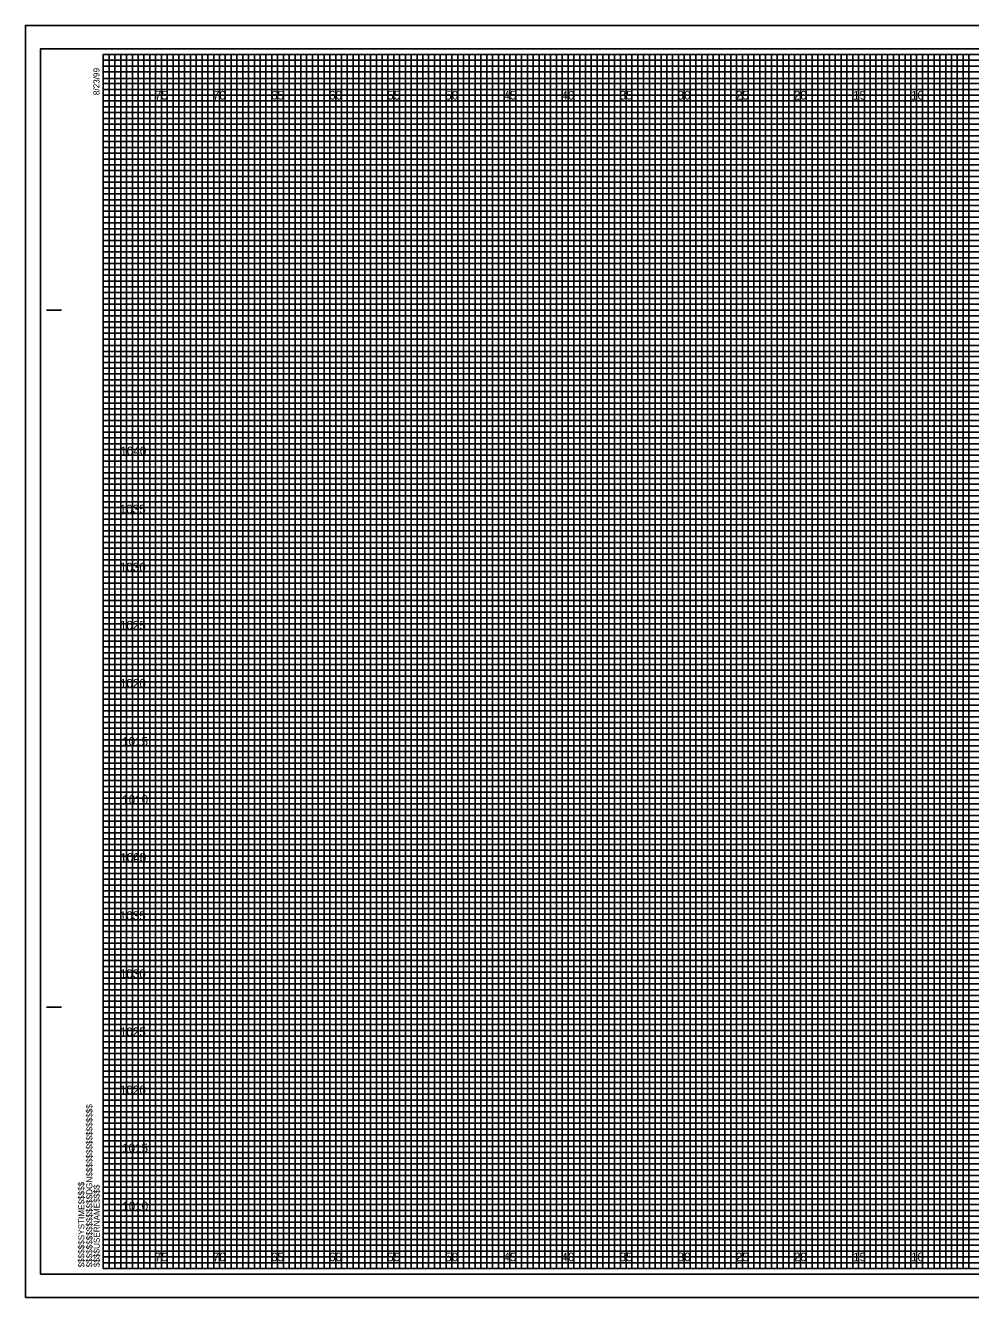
# Model space of a CAD drawing. Extents: x -7 to 162, y -2 to 987.
# Drawn here: x -6.7 to 74.6, y 217.5 to 327 of the extents above; entities that cross this region are included whole.
import ezdxf

# ---------------------------------------------------------------- set-up
doc = ezdxf.new("R2010")
doc.units = 0
for name, color, linetype in [('Exist Cross Section Cell', 7, 'Continuous'), ('Exist XS Center Line Elevation Label', 7, 'Continuous'), ('Exist XS Ground Line', 7, 'Continuous'), ('Prop CMT Concrete Structures', 7, 'Continuous'), ('Prop CMT Guardrail Widen Shoulder', 7, 'Continuous'), ('Prop CMT Pvmt Course 1', 7, 'Continuous'), ('Prop CMT Pvmt Surface', 7, 'Continuous'), ('Prop CMT Shld Paved Course 1', 7, 'Continuous'), ('Prop CMT Slope Grass', 7, 'Continuous'), ('Prop CMT Subgrade Earthwork', 7, 'Continuous'), ('Typical Text Label CELL', 7, 'Continuous')]:
    doc.layers.add(name, color=color, linetype=linetype)

msp = doc.modelspace()

# ---------------------------------------------------------------- linework, layer by layer
at = {"layer": 'Exist XS Center Line Elevation Label'}
for points in [[(0, 324.5), (2.5, 324.5), (2.5, 220), (7.5, 220), (7.5, 324.5), (12.5, 324.5), (12.5, 220), (17.5, 220), (17.5, 324.5), (22.5, 324.5), (22.5, 220), (27.5, 220), (27.5, 324.5), (32.5, 324.5), (32.5, 220), (37.5, 220), (37.5, 324.5), (42.5, 324.5), (42.5, 220), (47.5, 220), (47.5, 324.5), (52.5, 324.5), (52.5, 220), (57.5, 220), (57.5, 324.5), (62.5, 324.5), (62.5, 220), (67.5, 220), (67.5, 324.5), (72.5, 324.5), (72.5, 220), (77.5, 220)], [(0, 322), (137.5, 322)], [(0, 312.5), (160, 312.5), (160, 317.5), (0, 317.5)], [(0, 302.5), (160, 302.5), (160, 307.5), (0, 307.5)], [(0, 292.5), (160, 292.5), (160, 297.5), (0, 297.5)], [(0, 282.5), (160, 282.5), (160, 287.5), (0, 287.5)], [(0, 272.5), (160, 272.5), (160, 277.5), (0, 277.5)], [(0, 262.5), (160, 262.5), (160, 267.5), (0, 267.5)], [(0, 252.5), (160, 252.5), (160, 257.5), (0, 257.5)], [(0, 242.5), (160, 242.5), (160, 247.5), (0, 247.5)], [(0, 232.5), (160, 232.5), (160, 237.5), (0, 237.5)], [(0, 222.5), (160, 222.5), (160, 227.5), (0, 227.5)]]:
    msp.add_lwpolyline(points, dxfattribs=at)
at = {"layer": 'Exist XS Ground Line'}
for p, q in [((5, 324.5), (0, 324.5)), ((5, 220), (5, 324.5)), ((15, 324.5), (10, 324.5)), ((10, 324.5), (10, 220)), ((15, 220), (15, 324.5)), ((25, 324.5), (20, 324.5)), ((20, 324.5), (20, 220)), ((25, 220), (25, 324.5)), ((35, 324.5), (30, 324.5)), ((30, 324.5), (30, 220)), ((35, 220), (35, 324.5)), ((45, 324.5), (40, 324.5)), ((40, 324.5), (40, 220)), ((45, 220), (45, 324.5)), ((55, 324.5), (50, 324.5)), ((50, 324.5), (50, 220)), ((55, 220), (55, 324.5)), ((65, 324.5), (60, 324.5)), ((60, 324.5), (60, 220)), ((65, 220), (65, 324.5)), ((75, 324.5), (70, 324.5)), ((70, 324.5), (70, 220)), ((10, 220), (5, 220)), ((20, 220), (15, 220)), ((30, 220), (25, 220)), ((40, 220), (35, 220)), ((50, 220), (45, 220)), ((60, 220), (55, 220)), ((70, 220), (65, 220))]:
    msp.add_line(p, q, dxfattribs=at)
for points in [[(0, 320), (160, 320), (160, 315), (0, 315)], [(0, 310), (160, 310), (160, 305), (0, 305)], [(0, 300), (160, 300), (160, 295), (0, 295)], [(0, 290), (160, 290), (160, 285), (0, 285)], [(0, 280), (160, 280), (160, 275), (0, 275)], [(0, 270), (160, 270), (160, 265), (0, 265)], [(0, 260), (160, 260), (160, 255), (0, 255)], [(0, 250), (160, 250), (160, 245), (0, 245)], [(0, 240), (160, 240), (160, 235), (0, 235)], [(0, 230), (160, 230), (160, 225), (0, 225)]]:
    msp.add_lwpolyline(points, dxfattribs=at)
at = {"layer": 'Prop CMT Concrete Structures'}
for p, q in [((5, 220), (5, 324.5)), ((10, 220), (10, 324.5)), ((15, 220), (15, 324.5)), ((20, 220), (20, 324.5)), ((25, 220), (25, 324.5)), ((30, 220), (30, 324.5)), ((35, 220), (35, 324.5)), ((40, 220), (40, 324.5)), ((45, 220), (45, 324.5)), ((50, 220), (50, 324.5)), ((55, 220), (55, 324.5)), ((60, 220), (60, 324.5)), ((65, 220), (65, 324.5)), ((70, 220), (70, 324.5)), ((0, 320), (160, 320)), ((0, 315), (160, 315)), ((0, 310), (160, 310)), ((0, 305), (160, 305)), ((0, 300), (160, 300)), ((0, 295), (160, 295)), ((0, 290), (160, 290)), ((0, 285), (160, 285)), ((0, 280), (160, 280)), ((0, 275), (160, 275)), ((0, 270), (160, 270)), ((0, 265), (160, 265)), ((0, 260), (160, 260)), ((0, 255), (160, 255)), ((0, 250), (160, 250)), ((0, 245), (160, 245)), ((0, 240), (160, 240)), ((0, 235), (160, 235)), ((0, 230), (160, 230)), ((0, 225), (160, 225))]:
    msp.add_line(p, q, dxfattribs=at)
at = {"layer": 'Prop CMT Guardrail Widen Shoulder'}
for p, q in [((161.65, 327), (-6.7, 327)), ((-6.7, 327), (-6.7, 217.5)), ((-6.7, 217.5), (161.65, 217.5))]:
    msp.add_line(p, q, dxfattribs=at)
at = {"layer": 'Prop CMT Pvmt Course 1'}
msp.add_lwpolyline([(-6.7, 217.5), (161.65, 217.5), (161.65, 327), (-6.7, 327)], close=True, dxfattribs=at)
at = {"layer": 'Prop CMT Pvmt Surface'}
for points in [[(0, 220), (0.5, 220), (0.5, 324.5), (1, 324.5), (1, 220)], [(1, 220), (1.5, 220), (1.5, 324.5), (2, 324.5), (2, 220)], [(2.5, 220), (3, 220), (3, 324.5), (3.5, 324.5), (3.5, 220)], [(3.5, 220), (4, 220), (4, 324.5), (4.5, 324.5), (4.5, 220)], [(5, 220), (5.5, 220), (5.5, 324.5), (6, 324.5), (6, 220)], [(6, 220), (6.5, 220), (6.5, 324.5), (7, 324.5), (7, 220)], [(7.5, 220), (8, 220), (8, 324.5), (8.5, 324.5), (8.5, 220)], [(8.5, 220), (9, 220), (9, 324.5), (9.5, 324.5), (9.5, 220)], [(10, 220), (10.5, 220), (10.5, 324.5), (11, 324.5), (11, 220)], [(11, 220), (11.5, 220), (11.5, 324.5), (12, 324.5), (12, 220)], [(12.5, 220), (13, 220), (13, 324.5), (13.5, 324.5), (13.5, 220)], [(13.5, 220), (14, 220), (14, 324.5), (14.5, 324.5), (14.5, 220)], [(15, 220), (15.5, 220), (15.5, 324.5), (16, 324.5), (16, 220)], [(16, 220), (16.5, 220), (16.5, 324.5), (17, 324.5), (17, 220)], [(17.5, 220), (18, 220), (18, 324.5), (18.5, 324.5), (18.5, 220)], [(18.5, 220), (19, 220), (19, 324.5), (19.5, 324.5), (19.5, 220)], [(20, 220), (20.5, 220), (20.5, 324.5), (21, 324.5), (21, 220)], [(21, 220), (21.5, 220), (21.5, 324.5), (22, 324.5), (22, 220)], [(22.5, 220), (23, 220), (23, 324.5), (23.5, 324.5), (23.5, 220)], [(23.5, 220), (24, 220), (24, 324.5), (24.5, 324.5), (24.5, 220)], [(25, 220), (25.5, 220), (25.5, 324.5), (26, 324.5), (26, 220)], [(26, 220), (26.5, 220), (26.5, 324.5), (27, 324.5), (27, 220)], [(27.5, 220), (28, 220), (28, 324.5), (28.5, 324.5), (28.5, 220)], [(28.5, 220), (29, 220), (29, 324.5), (29.5, 324.5), (29.5, 220)], [(30, 220), (30.5, 220), (30.5, 324.5), (31, 324.5), (31, 220)], [(31, 220), (31.5, 220), (31.5, 324.5), (32, 324.5), (32, 220)], [(32.5, 220), (33, 220), (33, 324.5), (33.5, 324.5), (33.5, 220)], [(33.5, 220), (34, 220), (34, 324.5), (34.5, 324.5), (34.5, 220)], [(35, 220), (35.5, 220), (35.5, 324.5), (36, 324.5), (36, 220)], [(36, 220), (36.5, 220), (36.5, 324.5), (37, 324.5), (37, 220)], [(37.5, 220), (38, 220), (38, 324.5), (38.5, 324.5), (38.5, 220)], [(38.5, 220), (39, 220), (39, 324.5), (39.5, 324.5), (39.5, 220)], [(40, 220), (40.5, 220), (40.5, 324.5), (41, 324.5), (41, 220)], [(41, 220), (41.5, 220), (41.5, 324.5), (42, 324.5), (42, 220)], [(42.5, 220), (43, 220), (43, 324.5), (43.5, 324.5), (43.5, 220)], [(43.5, 220), (44, 220), (44, 324.5), (44.5, 324.5), (44.5, 220)], [(45, 220), (45.5, 220), (45.5, 324.5), (46, 324.5), (46, 220)], [(46, 220), (46.5, 220), (46.5, 324.5), (47, 324.5), (47, 220)], [(47.5, 220), (48, 220), (48, 324.5), (48.5, 324.5), (48.5, 220)], [(48.5, 220), (49, 220), (49, 324.5), (49.5, 324.5), (49.5, 220)], [(50, 220), (50.5, 220), (50.5, 324.5), (51, 324.5), (51, 220)], [(51, 220), (51.5, 220), (51.5, 324.5), (52, 324.5), (52, 220)], [(52.5, 220), (53, 220), (53, 324.5), (53.5, 324.5), (53.5, 220)], [(53.5, 220), (54, 220), (54, 324.5), (54.5, 324.5), (54.5, 220)], [(55, 220), (55.5, 220), (55.5, 324.5), (56, 324.5), (56, 220)], [(56, 220), (56.5, 220), (56.5, 324.5), (57, 324.5), (57, 220)], [(57.5, 220), (58, 220), (58, 324.5), (58.5, 324.5), (58.5, 220)], [(58.5, 220), (59, 220), (59, 324.5), (59.5, 324.5), (59.5, 220)], [(60, 220), (60.5, 220), (60.5, 324.5), (61, 324.5), (61, 220)], [(61, 220), (61.5, 220), (61.5, 324.5), (62, 324.5), (62, 220)], [(62.5, 220), (63, 220), (63, 324.5), (63.5, 324.5), (63.5, 220)], [(63.5, 220), (64, 220), (64, 324.5), (64.5, 324.5), (64.5, 220)], [(65, 220), (65.5, 220), (65.5, 324.5), (66, 324.5), (66, 220)], [(66, 220), (66.5, 220), (66.5, 324.5), (67, 324.5), (67, 220)], [(67.5, 220), (68, 220), (68, 324.5), (68.5, 324.5), (68.5, 220)], [(68.5, 220), (69, 220), (69, 324.5), (69.5, 324.5), (69.5, 220)], [(70, 220), (70.5, 220), (70.5, 324.5), (71, 324.5), (71, 220)], [(71, 220), (71.5, 220), (71.5, 324.5), (72, 324.5), (72, 220)], [(72.5, 220), (73, 220), (73, 324.5), (73.5, 324.5), (73.5, 220)], [(73.5, 220), (74, 220), (74, 324.5), (74.5, 324.5), (74.5, 220)]]:
    msp.add_lwpolyline(points, dxfattribs=at)
at = {"layer": 'Prop CMT Shld Paved Course 1'}
for p, q in [((0, 324), (130, 324)), ((130, 323.49), (0, 323.49)), ((0, 323.49), (0, 323)), ((0, 323), (130, 323)), ((130, 322.44), (0, 322.44)), ((0, 322.44), (0, 321.5)), ((0, 321.5), (160, 321.5))]:
    msp.add_line(p, q, dxfattribs=at)
for points in [[(0, 321), (135, 321), (160, 321), (160, 321), (0, 321)], [(0, 320.5), (160, 320.5), (160, 319.5), (0, 319.5)], [(0, 319), (160, 319), (160, 318.5), (0, 318.49)], [(0, 318), (160, 318), (160, 317), (0, 317)], [(0, 316.5), (160, 316.5), (160, 316), (0, 316)], [(0, 315.5), (160, 315.5), (160, 314.5), (0, 314.5)], [(0, 314), (160, 314), (160, 313.5), (0, 313.5)], [(0, 313), (160, 313), (160, 312), (0, 312)], [(0, 311.5), (160, 311.5), (160, 311), (0, 311)], [(0, 310.5), (160, 310.5), (160, 309.5), (0, 309.5)], [(0, 309), (160, 309), (160, 308.5), (0, 308.5)], [(0, 308), (160, 308), (160, 306.98), (160, 306.5), (160, 306), (0, 306)], [(0, 307), (160, 307), (160, 306.5), (0, 306.5)], [(0, 305.5), (160, 305.5), (160, 304.5), (0, 304.51)], [(0, 304.51), (160, 304.5), (160, 304), (0, 304)], [(0, 303.5), (160, 303.5), (160, 303), (0, 303)], [(0, 302), (160, 302), (160, 301.5), (0, 301.5)], [(0, 301), (160, 301), (160, 300.5), (0, 300.5)], [(-0.04, 299.44), (160, 299.44), (160, 298.94), (-0.04, 298.94)], [(0, 298.5), (160, 298.5), (160, 298), (0, 298)], [(0, 297), (160, 297), (160, 296.5), (0, 296.5)], [(0, 296), (160, 296), (160, 295.5), (0, 295.5)], [(0, 294.5), (160, 294.5), (160, 294), (0, 294)], [(0, 293.5), (160, 293.5), (160, 293), (0, 293)], [(0, 292), (160, 292), (160, 291.5), (0, 291.5)], [(0, 291), (160, 291), (160, 290.5), (0, 290.5)], [(0, 289.5), (160, 289.5), (160, 288.99), (0, 289)], [(0, 288.5), (160, 288.5), (160, 288), (0, 288)], [(0, 287), (160, 287), (160, 286.5), (0, 286.5)], [(0, 286), (160, 286), (160, 285.5), (0, 285.5)], [(0, 284.5), (160, 284.5), (160, 284), (0, 284)], [(0, 283.5), (160, 283.5), (160, 283), (0, 283)], [(0, 282), (160, 282), (160, 281.5), (0, 281.5)], [(0, 281), (160, 281), (160, 280.5), (0, 280.5)], [(0, 279.5), (160, 279.5), (160, 279), (0, 279)], [(0, 278.5), (160.03, 278.45), (160, 278), (0, 278)], [(0, 277), (160, 277), (160, 276.5), (0, 276.5)], [(0, 276), (160, 276), (160, 275.5), (0, 275.5)], [(0, 274.5), (160, 274.5), (160, 274), (0, 274)], [(0, 273.5), (160, 273.5), (160, 273), (0, 273)], [(0, 272), (160, 272), (160, 271.5), (0, 271.5)], [(0, 271), (160, 271), (160, 270.5), (0, 270.5)], [(0, 269.5), (160, 269.5), (160, 269), (0, 269)], [(0, 268.5), (160, 268.5), (160, 268), (0, 268)], [(0, 267), (160, 267), (160, 266.5), (0, 266.5)], [(0, 266), (160, 266), (160, 265.5), (0, 265.5)], [(0, 264.5), (160, 264.5), (160, 264), (0, 264)], [(0, 263.5), (160, 263.5), (160, 263), (0, 263)], [(0, 262), (160, 262), (160, 261.5), (0, 261.5)], [(0, 261), (160, 261), (160, 260.5), (0, 260.5)], [(0, 259.5), (160, 259.5), (160, 258.99), (0, 259)], [(0, 258.5), (160, 258.5), (160, 258), (0, 258)], [(0, 257), (160, 257), (160, 256.5), (0, 256.5)], [(0, 256), (160, 256), (160, 255.5), (0, 255.5)], [(0, 254.5), (160, 254.5), (160, 254), (0, 254)], [(0, 253.5), (160, 253.5), (160, 253), (0, 253)], [(0, 252), (160, 252), (160, 251.5), (0, 251.5)], [(0, 251), (160, 251), (160, 250.5), (0, 250.5)], [(0, 249.5), (160, 249.5), (160, 249), (0, 249)], [(0, 248.5), (160.03, 248.46), (160, 248), (0, 248)], [(0, 247), (160, 247), (160, 246.5), (0, 246.5)], [(0, 246), (160, 246), (160, 245.5), (0, 245.5)], [(0, 244.5), (160, 244.5), (160, 244), (0, 244)], [(0, 243.5), (160, 243.5), (160, 243), (0, 243)], [(0, 242), (160, 242), (160, 241.5), (0, 241.5)], [(0, 241), (160, 241), (160, 240.5), (0, 240.5)], [(0, 239.5), (160, 239.5), (160, 239), (0, 239)], [(0, 238.5), (160, 238.5), (160, 238), (0, 238)], [(0, 237), (160, 237), (160, 236.5), (0, 236.5)], [(0, 236), (160, 236), (160, 235.5), (0, 235.5)], [(0, 234.5), (160, 234.5), (160, 234), (0, 234)], [(0, 233.5), (160, 233.5), (160, 233), (0, 233)], [(0, 232), (160, 232), (160, 231.5), (0, 231.5)], [(0, 231), (160, 231), (160, 230.5), (0, 230.5)], [(0, 229.5), (160, 229.5), (160, 229), (0, 229)], [(0, 228.5), (160, 228.5), (160, 228), (0, 228)], [(0, 227), (160, 227), (160, 226.5), (0, 226.5)], [(0, 226), (160, 226), (160, 225.5), (0, 225.5)], [(0, 224.5), (160, 224.5), (160, 224), (0, 224)], [(0, 223.5), (160, 223.5), (160, 223), (0, 223)], [(0, 222), (160, 222), (160, 221.5), (0, 221.5)], [(0, 221), (160, 221), (160, 220.5), (0, 220.5)]]:
    msp.add_lwpolyline(points, dxfattribs=at)
at = {"layer": 'Prop CMT Slope Grass'}
msp.add_lwpolyline([(-5.4, 219.5), (161.2, 219.5), (161.2, 325), (-5.4, 325)], close=True, dxfattribs=at)
at = {"layer": 'Prop CMT Subgrade Earthwork'}
for p, q in [((-4.9, 302.5), (-3.65, 302.5)), ((-4.85, 302.5), (-3.6, 302.5)), ((-4.9, 242.5), (-3.65, 242.5)), ((-4.85, 242.5), (-3.6, 242.5)), ((0, 220), (0, 220)), ((0, 220), (0, 220)), ((0, 220), (0, 220)), ((0, 220), (0, 220)), ((0, 220), (0, 220)), ((0, 220), (0, 220)), ((0, 220), (0, 220))]:
    msp.add_line(p, q, dxfattribs=at)
msp.add_lwpolyline([(160, 324.5), (0, 324.5), (0, 220), (160, 220)], close=True, dxfattribs=at)

# ---------------------------------------------------------------- texts
at = {"layer": 'Exist Cross Section Cell'}
for s, p in [('75', (4.44, 320.62)), ('70', (9.43, 320.62)), ('65', (14.44, 320.62)), ('60', (19.43, 320.62)), ('55', (24.44, 320.62)), ('50', (29.43, 320.62)), ('45', (34.44, 320.62)), ('40', (39.43, 320.62)), ('35', (44.44, 320.62)), ('30', (49.43, 320.62)), ('25', (54.44, 320.62)), ('20', (59.43, 320.62)), ('15', (64.53, 320.62)), ('10', (69.52, 320.62)), ('75', (4.44, 220.62)), ('70', (9.43, 220.62)), ('65', (14.44, 220.62)), ('60', (19.43, 220.62)), ('55', (24.44, 220.62)), ('50', (29.43, 220.62)), ('45', (34.44, 220.62)), ('40', (39.43, 220.62)), ('35', (44.44, 220.62)), ('30', (49.43, 220.62)), ('25', (54.44, 220.62)), ('20', (59.43, 220.62)), ('15', (64.53, 220.62)), ('10', (69.52, 220.62))]:
    msp.add_text(s, height=0.75, dxfattribs=at).set_placement(p)
at = {"layer": 'Prop CMT Subgrade Earthwork'}
for s, p in [('8/23/99', (-0.33, 321)), ('$$$$$$$$$$$$$$$$DGN$$$$$$$$$$$$$$$$', (-0.94, 220.09)), ('$$$$$$SYSTIME$$$$$', (-1.63, 220.09)), ('$$$$USERNAME$$$$', (-0.31, 220.12))]:
    msp.add_text(s, height=0.525, rotation=90, dxfattribs=at).set_placement(p)
at = {"layer": 'Typical Text Label CELL'}
for s, p in [('1040', (1.47, 290)), ('1035', (1.42, 285)), ('1030', (1.43, 280)), ('1025', (1.43, 275)), ('1020', (1.44, 270)), ('1015', (1.62, 265)), ('1010', (1.63, 260)), ('1005', (1.45, 255)), ('1040', (1.47, 255)), ('1035', (1.42, 250)), ('1030', (1.43, 245)), ('1025', (1.43, 240)), ('1020', (1.44, 235)), ('1015', (1.62, 230)), ('1010', (1.63, 225))]:
    msp.add_text(s, height=0.75, dxfattribs=at).set_placement(p)

doc.saveas('drawing.dxf')
